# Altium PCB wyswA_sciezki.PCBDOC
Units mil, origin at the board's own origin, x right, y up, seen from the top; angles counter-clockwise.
Board outline 7130 x 4885 mil, 2 copper layers (Top Layer, Bottom Layer); 14 components, 44 nets, 417 pads, 152 vias.
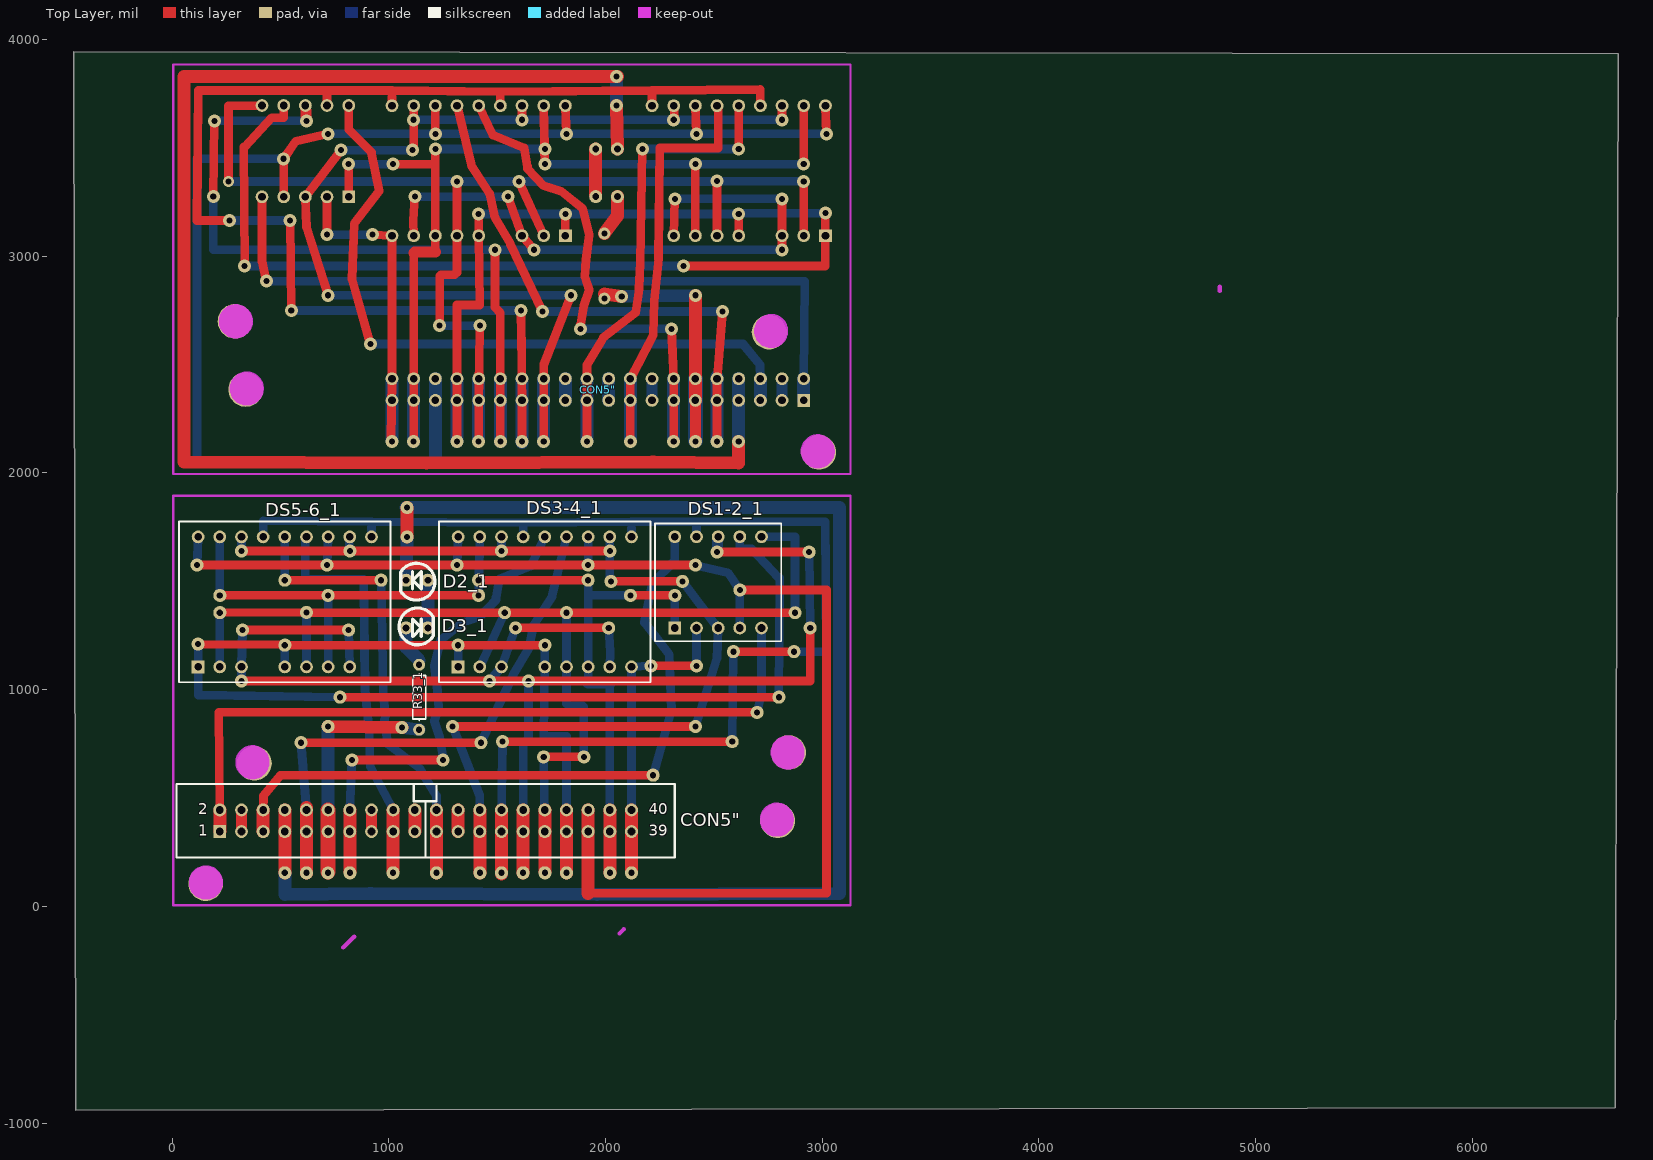
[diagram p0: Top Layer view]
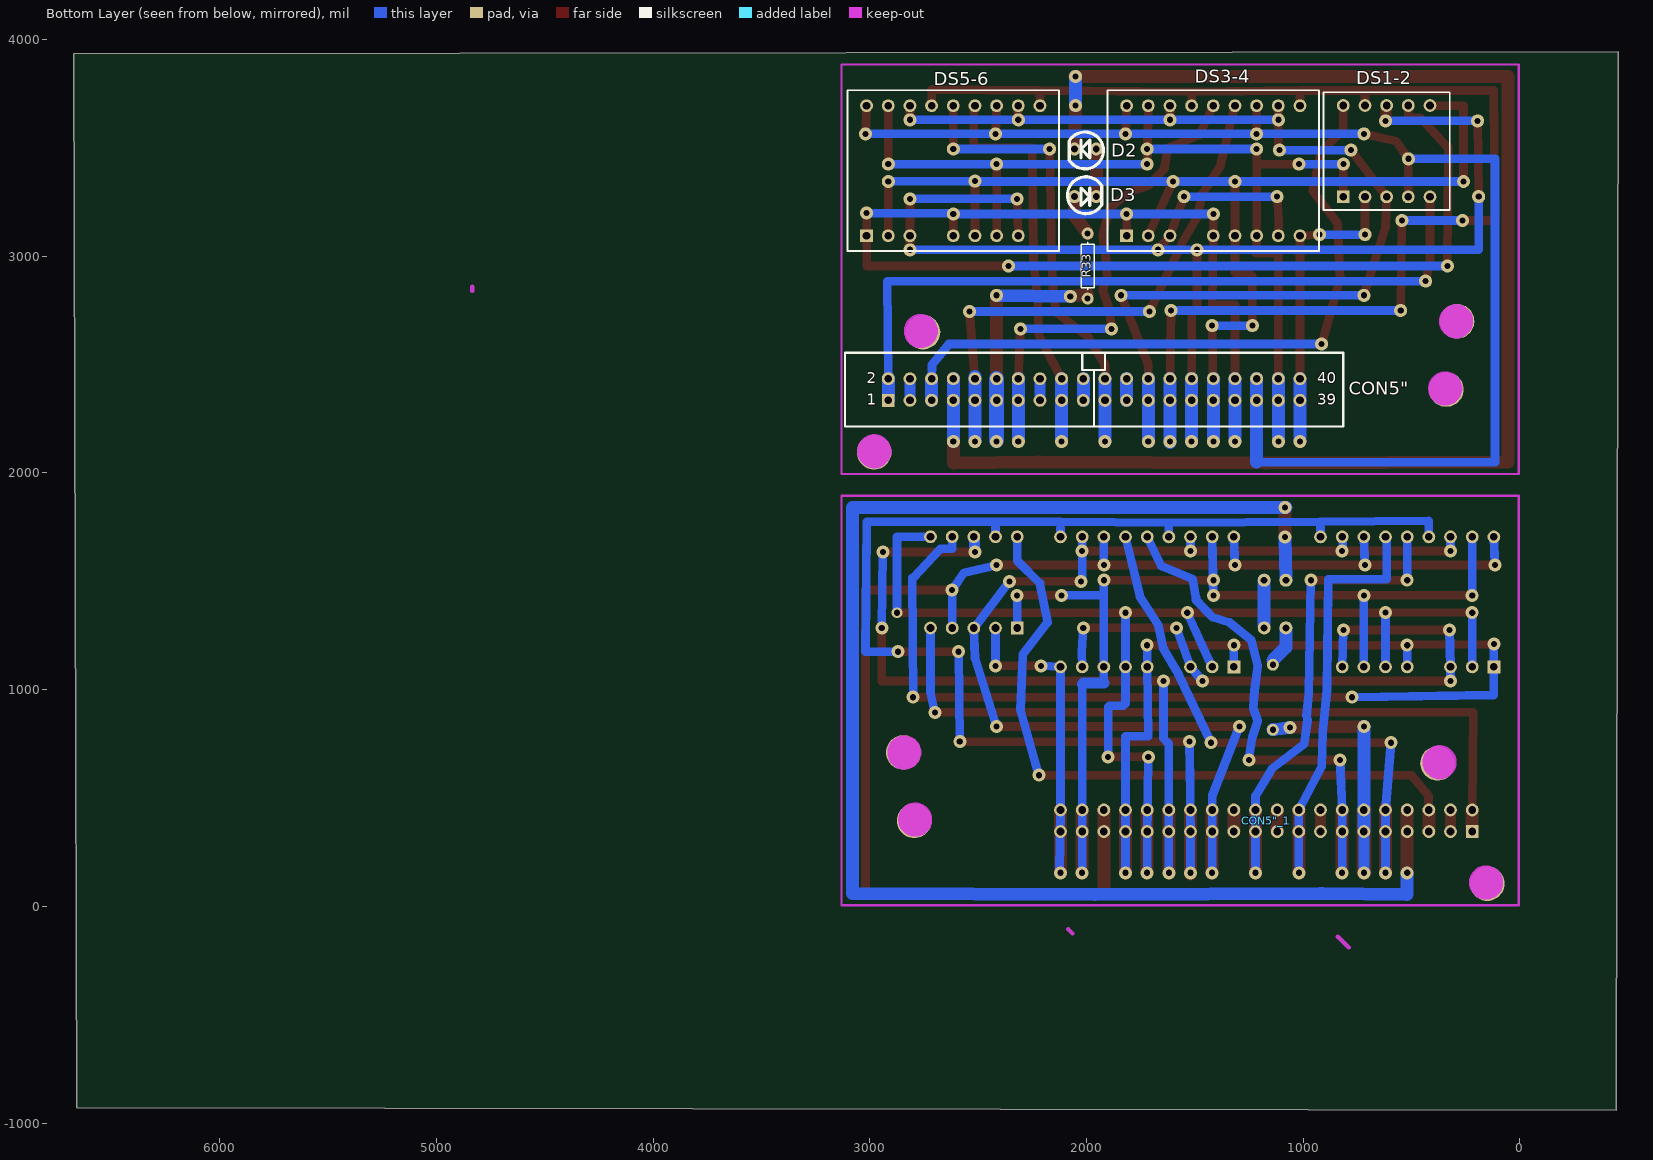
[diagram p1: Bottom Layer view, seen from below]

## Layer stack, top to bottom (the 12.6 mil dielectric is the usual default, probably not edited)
Top Layer: signal copper 1.4
Dielectric: dielectric 12.6, FR-4, Dk 4.8
Bottom Layer: signal copper 1.4

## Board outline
-445,-940 6660,-930 6675,3935 -455,3945

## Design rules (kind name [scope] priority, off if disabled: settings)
Clearance [All] p1: gap=10
ComponentClearance [All] p1: gap=1 collisioncheckmode=0
PolygonConnect [All] p1: connectstyle=Relief reliefconductorwidth=10 reliefentries=4 polygonreliefangle="90 Angle"
RoutingLayers [All] p1: top layer=Horizontal bottom layer=Vertical
RoutingVias [All] p1: holewidth=28 width=50 viastyle="Through Hole" minholewidth=28 minwidth=50 maxholewidth=28 maxwidth=50
SolderMaskExpansion [All] p1: expansion=4
TestPointUsage [All] p1: valid=0 allowmultiple=FALSE
Testpoint [All] p1: side=15 testpointundercomponent=TRUE minsize=40 maxsize=100 preferedsize=60 minholesize=0 maxholesize=40 preferedholesize=32 testpointgrid=1 style=1023 order=1234567890
Width [All] p1: maxlimit=90 minlimit=10 preferedwidth=10 toplayer_prefwidth=50 bottomlayer_prefwidth=50 minimp=50.000000 maximp=50.000000 favimp=50.000000
16 further rules are at their usual default settings.

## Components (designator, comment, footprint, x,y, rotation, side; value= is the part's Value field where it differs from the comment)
"CON5\"" "Header 20X2H" HDR2X20_gn_pra 1015,2335 r0 top
"CON5\"_1" "Header 20X2H" HDR2X20_gn_pra 2120,345 r180 bottom
D2 "LED_3" LED3 1955,3495 r180 bottom (schematic designator D3)
D2_1 "LED_3" LED3 1180,1505 r0 top (schematic designator D3)
D3 "LED_3" LED3 2055,3275 r0 bottom (schematic designator D4)
D3_1 "LED_3" LED3 1080,1285 r180 top (schematic designator D4)
DS1-2 "*" LEDDIP-DA/DC36 615,3485 r180 bottom (schematic designator DS12)
DS1-2_1 "*" LEDDIP-DA/DC36 2520,1495 r0 top (schematic designator DS12)
DS3-4 "*" LEDDIP-DA/DC56#1 1415,3395 r180 bottom (schematic designator DS34)
DS3-4_1 "*" LEDDIP-DA/DC56#1 1720,1405 r0 top (schematic designator DS34)
DS5-6 "*" LEDDIP-DA/DC56#2 2615,3395 r180 bottom (schematic designator DS56)
DS5-6_1 "*" LEDDIP-DA/DC56#2 520,1405 r0 top (schematic designator DS56)
R33 "Res2" AXIAL-0.3 1995,2955 r90 bottom
R33_1 "Res2" AXIAL-0.3 1140,965 r90 top (schematic designator R33)

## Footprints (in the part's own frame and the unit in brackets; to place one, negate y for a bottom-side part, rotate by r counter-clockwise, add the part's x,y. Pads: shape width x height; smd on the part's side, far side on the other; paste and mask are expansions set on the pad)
AXIAL-0.3 [mm]
  round 1.4 hole 0.711: 1(-3.81,0) 2(3.81,0)
  silkscreen extent -2.77,-0.76 2.77,0.76
HDR2X20_gn_pra [mm]
  rect 1.5x1.5 hole 0.9: 1(48.26,0)
  round 1.5 hole 0.9: 2(48.26,2.54) 3(45.72,0) 4(45.72,2.54) 5(43.18,0) 6(43.18,2.54) 7(40.64,0) 8(40.64,2.54) 9(38.1,0) 10(38.1,2.54) 11(35.56,0) 12(35.56,2.54) 13(33.02,0) 14(33.02,2.54) 15(30.48,0) 16(30.48,2.54) 17(27.94,0) 18(27.94,2.54) 19(25.4,0) 20(25.4,2.54) 21(22.86,0) 22(22.86,2.54) 23(20.32,0) 24(20.32,2.54) 25(17.78,0) 26(17.78,2.54) 27(15.24,0) 28(15.24,2.54) 29(12.7,0) 30(12.7,2.54) 31(10.16,0) 32(10.16,2.54) 33(7.62,0) 34(7.62,2.54) 35(5.08,0) 36(5.08,2.54) 37(2.54,0) 38(2.54,2.54) 39(0,0) 40(0,2.54)
LED3 [mil]
  round 60 hole 32: 1(0,0) 2(-100,0)
  silkscreen extent -125,-92 33,78
LEDDIP-DA/DC36 [mm]
  rect 1.5x1.5 hole 0.9: 1(-5.08,-5.35)
  round 1.5 hole 0.9: 2(-2.54,-5.35) 3(0,-5.35) 4(2.54,-5.35) 5(5.08,-5.35) 6(5.08,5.35) 7(2.54,5.35) 8(0,5.35) 9(-2.54,5.35) 10(-5.08,5.35)
  silkscreen extent -7.4,-6.9 7.4,6.9
LEDDIP-DA/DC56#1 [mm]
  rect 1.5x1.5 hole 0.9: 1(-10.16,-7.62)
  round 1.5 hole 0.9: 2(-7.62,-7.62) 3(-5.08,-7.62) 5(0,-7.62) 6(2.54,-7.62) 7(5.08,-7.62) 8(7.62,-7.62) 9(10.16,-7.62) 10(10.16,7.62) 11(7.62,7.62) 12(5.08,7.62) 13(2.54,7.62) 14(0,7.62) 15(-2.54,7.62) 16(-5.08,7.62) 17(-7.62,7.62) 18(-10.16,7.62)
  silkscreen extent -12.4,-9.43 12.4,9.43
LEDDIP-DA/DC56#2 [mm]
  rect 1.5x1.5 hole 0.9: 1(-10.16,-7.62)
  round 1.5 hole 0.9: 2(-7.62,-7.62) 3(-5.08,-7.62) 5(0,-7.62) 6(2.54,-7.62) 7(5.08,-7.62) 8(7.62,-7.62) 10(10.16,7.62) 11(7.62,7.62) 12(5.08,7.62) 13(2.54,7.62) 14(0,7.62) 15(-2.54,7.62) 16(-5.08,7.62) 17(-7.62,7.62) 18(-10.16,7.62)
  silkscreen extent -12.4,-9.43 12.4,9.43

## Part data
D2 D2_1 D3 D3_1: "Typical RED, GREEN, YELLOW, AMBER GaAs LED"
DS1-2 DS1-2_1: library part DA36, "Common Anode Dual Seven-Segment Display, Right Hand Decimal"
DS3-4 DS3-4_1 DS5-6 DS5-6_1: library part DA56, "Common Anode Dual Seven-Segment Display, Right Hand Decimal"
R33 R33_1: "Resistor"

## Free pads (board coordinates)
  round 60 smd: 0(220,345) 0(1060,825) 0(1645,1040) 1(720,830) 1(1220,445) 1(1520,1640) 1(1920,445) 1(2220,605) 2(820,1640) 2(1920,345) 3(520,155) 3(1535,1355) 4(620,155) 4(2020,445) 4(2700,895) 5(2020,345) 6(820,155) 6(1920,1575) 8(720,1435) 8(1020,155) 9(115,1575) 10(715,1575) 10(1220,155) 11(1315,1575) 12(1085,1840) 12(1420,155) 12(1920,1575) 13(1085,1705) 13(1520,155) 13(2415,1575) 14(1620,155) 14(2620,1460) 15(1720,155) 15(2020,1640) 16(1820,155) 18(2020,155) 18(2120,445) 18(2515,1635) 19(2120,155) 19(2120,345) 20(2210,1110) 21(2420,1110) 23(1820,445) 24(1820,345) 26(1720,445) 27(1720,345) 28(1720,345) 29(1715,690) 30(1900,690) 32(1620,445) 33(1620,345) 35(2945,1285) 37(1520,445) 38(1415,1505) 38(1520,345) 39(1920,1505) 39(2585,760) 40(2025,1500) 41(1420,445) 41(2355,1500) 42(220,1435) 42(1420,345) 43(1295,830) 44(1415,1435) 44(2415,830) 45(2025,1500) 45(2115,1435) 46(2320,1435) 46(2355,1500) 47(220,1355) 48(619.99,1356.48) 49(1820,1355) 50(2875,1355) 51(325,1275) 52(815,1275) 53(520,445) 53(1585,1285) 54(2015,1285) 55(120,1210) 55(520,345) 56(520,1205) 57(1720,1205) 58(1220,345) 58(2590,1175) 59(965,1505) 60(520,1505) 62(2800,965) 63(775,965) 64(320,1040) 65(720,445) 66(720,345) 67(2420,1110) 68(2870,1175) 70(1320,1205) 71(220,445) 73(1465,1040) 77(420,445) 78(420,345) 80(620,445) 81(620,345) 82(595,755) 83(1425,755) 84(820,445) 86(820,345) 87(830,675) 88(1250,675) 89(1020,445) 91(1020,345) 98(320,1640) 100(2940,1635) 101(1525,760)
  round 30 on Keep-Out: 0(1490,-110)
  round 60 smd far side: 0(1490,3030) 0(2075,2815) 0(2915,2335) 1(915,2595) 1(1215,2435) 1(1615,3630) 1(1915,2435) 1(2415,2820) 2(1215,2335) 2(2315,3630) 3(1600,3345) 3(2615,2145) 4(435,2885) 4(1115,2435) 4(2515,2145) 5(1115,2335) 6(1215,3565) 6(2315,2145) 8(2115,2145) 8(2415,3425) 9(3020,3565) 10(1915,2145) 10(2420,3565) 11(1820,3565) 12(1215,3565) 12(1715,2145) 12(2050,3830) 13(720,3565) 13(1615,2145) 13(2050,3695) 14(515,3450) 14(1515,2145) 15(1115,3630) 15(1415,2145) 16(1315,2145) 18(620,3625) 18(1015,2435) 18(1115,2145) 19(1015,2145) 19(1015,2335) 20(925,3100) 21(715,3100) 23(1315,2435) 24(1315,2335) 26(1415,2435) 27(1415,2335) 28(1415,2335) 29(1420,2680) 30(1235,2680) 32(1515,2435) 33(1515,2335) 35(190,3275) 37(1615,2435) 38(1615,2335) 38(1720,3495) 39(550,2750) 39(1215,3495) 40(1110,3490) 41(780,3490) 41(1715,2435) 42(1715,2335) 42(2915,3425) 43(1840,2820) 44(720,2820) 44(1720,3425) 45(1020,3425) 45(1110,3490) 46(780,3490) 46(815,3425) 47(2915,3345) 48(2515.01,3346.48) 49(1315,3345) 50(260,3345) 51(2815,3265) 52(2320,3265) 53(1550,3275) 53(2615,2435) 54(1120,3275) 55(2615,2335) 55(3015,3200) 56(2615,3195) 57(1415,3195) 58(545,3165) 58(1915,2335) 59(2170,3495) 60(2615,3495) 62(335,2955) 63(2360,2955) 64(2815,3030) 65(2415,2435) 66(2415,2335) 67(715,3100) 68(265,3165) 70(1815,3195) 71(2915,2435) 73(1670,3030) 77(2715,2435) 78(2715,2335) 80(2515,2435) 81(2515,2335) 82(2540,2745) 83(1710,2745) 84(2315,2435) 86(2315,2335) 87(2305,2665) 88(1885,2665) 89(2115,2435) 91(2115,2335) 98(2815,3630) 100(195,3625) 101(1610,2750)
  round 160 smd: 9(290,2700) 10(340,2385) 11(2755,2650) 12(2985,2095) 13(380,660) 14(2845,710) 15(2795,395) 16(155,105)
  round 160 smd far side: 9(2845,710) 10(2795,395) 11(380,660) 12(150,105) 13(2755,2650) 14(290,2700) 15(340,2385) 16(2980,2095)

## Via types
v1: diameter 60, hole 28, Top Layer to Bottom Layer, 148 vias
v2: diameter 50, hole 28, Top Layer to Bottom Layer, 4 vias

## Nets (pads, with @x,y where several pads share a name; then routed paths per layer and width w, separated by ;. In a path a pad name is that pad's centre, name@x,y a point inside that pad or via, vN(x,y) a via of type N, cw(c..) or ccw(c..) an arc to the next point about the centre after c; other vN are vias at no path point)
A: 
"A1\"": "CON5\".1" "CON5\".2" DS1-2.5 pad.0@2915,2335 pad.4@435,2885 pad.71@2915,2435 | length 3451.6
  Top Layer w40: DS1-2.5 415,2975 v1(435,2885)
  Bottom Layer w40: v1(435,2885) 1350,2885 ; 1325,2885 2920,2885 v2(2915,2435)
  Bottom Layer w60: pad.0@2915,2335 v2(2915,2435)
"A2\"": "CON5\".5" "CON5\".6" DS1-2.10 pad.1@915,2595 pad.77@2715,2435 pad.78@2715,2335 | length 3206.5
  Top Layer w40: DS1-2.10 815,3585 920,3480 955,3300 840,3150 830,2895 v1(915,2595)
  Bottom Layer w40: v1(915,2595) 2635,2595 2713.09,2499.94 pad.77@2715,2435
  Bottom Layer w60: pad.78@2715,2335 pad.77@2715,2435
"A3\"": "CON5\".9" "CON5\".10" DS3-4.13 pad.4@2515,2145 pad.80@2515,2435 pad.81@2515,2335 pad.82@2540,2745 pad.83@1710,2745 | length 2749.7
  Top Layer w40: DS3-4.13 1380,3425 ; 1380,3420 1465,3290 1490,3180 1560,3060 v1(1710,2745) ; v1(2515,2145) 2515,2320 ; 2515,2335 2515,2435 v1(2540,2745)
  Bottom Layer w40: v1(1710,2745) v1(2540,2745)
  Bottom Layer w60: v1(2515,2145) 2515,2335 pad.80@2515,2445
"A4\"": "CON5\".13" "CON5\".14" DS3-4.14 pad.6@2315,2145 pad.84@2315,2435 pad.86@2315,2335 pad.87@2305,2665 pad.88@1885,2665 | length 2488.3
  Top Layer w40: DS3-4.14 1480,3560 1625,3500 1640,3415 ; 1640,3405 1715,3325 1795,3300 1895,3220 1925,3100 1910,2985 1905,2905 1925,2845 1900,2770 v1@1885,2685 ; v1(2305,2665) 2315,2435 2315,2335 v1(2315,2145)
  Bottom Layer w40: v1(1885,2665) v1(2305,2665)
  Bottom Layer w60: pad.6@2315,2150 2315,2335 pad.84@2315,2435
"A5\"": "CON5\".17" "CON5\".18" DS5-6.13 pad.8@2115,2145 pad.89@2115,2435 pad.91@2115,2335 | length 2107
  Top Layer w40: v1@2115,2155 2115,2335 2115,2435 2220,2635 2225,2795 2245,2990 2250,3500 2520,3500 DS5-6.13@2520,3680
  Bottom Layer w60: pad.8@2115,2155 pad.91@2115,2335 ; pad.91@2115,2330 pad.89@2115,2435
  other v1: 2115,2145
"A6\"": "CON5\".21" "CON5\".22" DS5-6.14 pad.1@1915,2435 pad.10@1915,2145 pad.58@1915,2335 pad.59@2170,3495 pad.60@2615,3495 | length 2379.9
  Top Layer w40: v1@1915,2140 1915,2335 1915,2500 1985,2615 ; 1990,2625 2140,2740 2155,2850 2160,2970 v1(2170,3495) ; v1(2615,3495) DS5-6.14
  Bottom Layer w40: v1(2170,3495) pad.60@2620,3495
  Bottom Layer w60: v1(1915,2145) 1915,2335 pad.1@1915,2435
A7: 
A8: 
A9: 
A10: 
A11: 
A12: 
"A\"": "CON5\".25" "CON5\".26" DS1-2.3 DS3-4.11 DS3-4.16 DS5-6.11 DS5-6.16 pad.1@1615,3630 pad.2@2315,3630 pad.12@1715,2145 pad.15@1115,3630 pad.40@1110,3490 pad.41@780,3490 pad.41@1715,2435 pad.42@1715,2335 pad.43@1840,2820 pad.44@720,2820 pad.45@1110,3490 pad.46@780,3490 pad.98@2815,3630 | length 5260.2
  Top Layer w40: v1(720,2820) 620,3135 DS1-2.3 v1(780,3490) ; v1@1115,3500 DS3-4.11 ; v1(1615,3630) DS3-4.16 ; v1@1715,2140 1715,2335 1715,2500 v1(1840,2820) ; DS5-6.11 v1@2320,3635 ; v1(2815,3630) DS5-6.16
  Bottom Layer w40: v1(720,2820) v1(1840,2820) ; v1(780,3490) pad.40@1100,3490 ; v1(1115,3630) v1(2815,3630)
  Bottom Layer w60: v1(1715,2145) 1715,2335 pad.41@1715,2435
  other v1: 1110,3490 2315,3630
B: 
"B\"": "CON5\".27" "CON5\".28" DS1-2.9 DS3-4.10 DS3-4.15 DS5-6.10 DS5-6.15 pad.13@1615,2145 pad.37@1615,2435 pad.38@1615,2335 pad.39@550,2750 pad.58@545,3165 pad.68@265,3165 pad.101@1610,2750 | length 6249.5
  Top Layer w40: 120,3760 115,3165 v1(265,3165) ; 120,3765 710,3765 1015,3765 1520,3760 2215,3765 2715,3770 DS5-6.15 ; v1(545,3165) v1(550,2750) ; DS1-2.9 715,3740 ; DS3-4.10 1015,3735 ; DS3-4.15 1515,3745 ; v1(1610,2750) 1612.95,2504.98 1613.8,2434.99 1615,2335 v1(1615,2145) ; DS5-6.10 2215,3740
  Bottom Layer w40: v1(265,3165) v1(545,3165) ; v1(550,2750) v1(1610,2750)
  Bottom Layer w60: pad.13@1615,2140 1615,2320 pad.37@1615,2435
C: 
"C\"": "CON5\".29" "CON5\".30" DS1-2.8 DS3-4.3 DS3-4.8 DS5-6.3 DS5-6.8 pad.0@1490,3030 pad.14@1515,2145 pad.18@620,3625 pad.32@1515,2435 pad.33@1515,2335 pad.35@190,3275 pad.51@2815,3265 pad.52@2320,3265 pad.53@1550,3275 pad.54@1120,3275 pad.64@2815,3030 pad.73@1670,3030 pad.100@195,3625 | length 6685.2
  Top Layer w30: DS3-4.8@1110,3090 DS3-4.8
  Top Layer w40: v1(190,3275) v1(195,3625) ; DS3-4.8 1112.27,3164.93 v1(1120,3275) ; v1@1490,3025 1490,2765 1515,2740 1515,2335 v1(1515,2145) ; v1(1550,3275) DS3-4.3 v1(1670,3030) ; DS5-6.8 v1(2320,3265) ; v1(2815,3030) DS5-6.3 v1(2815,3265)
  Top Layer w50: DS1-2.8 v1(620,3625)
  Bottom Layer w40: v1(190,3275) 190,3030 v1(1490,3030) pad.73@1665,3030 ; v1(195,3625) v1(620,3625) ; v1(1120,3275) v1(1550,3275) ; v1(1670,3030) v1(2815,3030) ; v1(2320,3265) v1(2815,3265)
  Bottom Layer w60: v1(1515,2145) 1515,2335 pad.32@1515,2435
D: 
"D\"": "CON5\".31" "CON5\".32" DS1-2.6 DS3-4.2 DS3-4.6 DS5-6.2 DS5-6.6 pad.3@1600,3345 pad.15@1415,2145 pad.26@1415,2435 pad.27@1415,2335 pad.28@1415,2335 pad.29@1420,2680 pad.30@1235,2680 pad.47@2915,3345 pad.48@2515.01,3346.48 pad.49@1315,3345 pad.50@260,3345 | length 5631.7
  Top Layer w40: v2(260,3345) 260,3695 DS1-2.6 ; v1@1235,2700 1235,2910 ; 1240,2915 1305,2915 ; 1315,2925 DS3-4.6 v1(1315,3345) ; v1@1415,2150 1415,2335 1416.45,2434.98 1417.39,2499.97 v1(1420,2680) ; v1(1600,3345) DS3-4.2 ; DS5-6.6 v1(2515.01,3346.48) ; DS5-6.2 v1(2915,3345)
  Bottom Layer w40: v2(260,3345) pad.48@2515.01,3345 ; v1(1235,2680) v1(1420,2680) ; v1(2515.01,3346.48) v1(2915,3345)
  Bottom Layer w60: pad.15@1415,2150 1415,2335 pad.26@1415,2435
  other v1: 1415,2145
DP: 
"DP\"": "CON5\".39" "CON5\".40" DS1-2.2 DS3-4.9 pad.18@1015,2435 pad.19@1015,2145 pad.19@1015,2335 pad.20@925,3100 pad.21@715,3100 pad.67@715,3100 | length 1689.6
  Top Layer w40: v1(715,3100) DS1-2.2@715,3259.37 ; v1(925,3100) DS3-4.9 1015,2505 1015,2435 v1@1010,2150
  Bottom Layer w40: v1(715,3100) v1(925,3100)
  Bottom Layer w60: pad.19@1015,2150 1015,2335 pad.18@1015,2435
  other v1: 1015,2145
E: 
"E\"": "CON5\".33" "CON5\".34" DS1-2.7 DS3-4.1 DS3-4.5 DS5-6.1 DS5-6.5 pad.16@1315,2145 pad.23@1315,2435 pad.24@1315,2335 pad.55@3015,3200 pad.56@2615,3195 pad.57@1415,3195 pad.62@335,2955 pad.63@2360,2955 pad.70@1815,3195 | length 6984.7
  Top Layer w40: 330,3505 v1(335,2955) ; 335,3505 460,3640 515,3640 DS1-2.7 ; v1(1315,2145) 1315,2335 1315,2765 ; 1315,2775 1420,2775 DS3-4.5 ; DS3-4.5@1415,3105 v1(1415,3195) ; DS3-4.1 v1(1815,3195) ; v1(2360,2955) 3015,2955 DS5-6.1 v1(3015,3200) ; DS5-6.5@2615,3105 v1(2615,3195)
  Bottom Layer w40: v1(335,2955) v1(2360,2955) ; v1(1415,3195) v1(1815,3195) v1(2615,3195) ; pad.56@2614.98,3197.49 v1(3015,3200)
  Bottom Layer w60: v1(1315,2145) 1315,2335 pad.23@1315,2435
F: 
"F\"": "CON5\".35" "CON5\".36" DS1-2.4 DS3-4.12 DS3-4.18 DS5-6.12 DS5-6.18 pad.1@1215,2435 pad.2@1215,2335 pad.6@1215,3565 pad.9@3020,3565 pad.10@2420,3565 pad.11@1820,3565 pad.12@1215,3565 pad.13@720,3565 pad.14@515,3450 | length 6522
  Top Layer w40: DS1-2.4 v1(515,3450) 570,3530 v1(720,3565) ; v1@1215,3575 DS3-4.12 ; DS3-4.18 v1(1820,3565) ; DS5-6.12 v1(2420,3565) ; DS5-6.18 v1(3020,3565)
  Bottom Layer w40: v1(515,3450) 115,3450 115,2050 1215,2050 ; v1(720,3565) v1(3020,3565)
  Bottom Layer w60: 1215,2050 pad.1@1215,2435
  other v1: 1215,3565
G: 
"G\"": "CON5\".37" "CON5\".38" DS1-2.1 DS3-4.7 DS3-4.17 DS5-6.7 DS5-6.17 pad.4@1115,2435 pad.5@1115,2335 pad.8@2415,3425 pad.18@1115,2145 pad.38@1720,3495 pad.39@1215,3495 pad.42@2915,3425 pad.44@1720,3425 pad.45@1020,3425 pad.46@815,3425 | length 4857.7
  Top Layer w40: DS1-2.1 v1(815,3425) ; v1(1020,3425) 1215,3425 ; v1(1115,2145) 1115,2335 1115,3015 ; 1215,3020 v1(1215,3495) ; DS3-4.17 1718.61,3499.97 v1(1720,3425) ; DS5-6.7 v1(2415,3425) ; v1(2915,3425) DS5-6.17
  Top Layer w50: 1115,3015 1120,3020 1215,3020
  Bottom Layer w40: v1(815,3425) v1(1020,3425) ; v1(1215,3495) v1(1720,3495) ; v1(1720,3425) v1(2915,3425)
  Bottom Layer w60: v1(1115,2145) 1115,2335 pad.4@1115,2435
GND: 
"GND\"": "CON5\".7" "CON5\".8" D2.2 pad.3@2615,2145 pad.12@2050,3830 pad.13@2050,3695 pad.53@2615,2435 pad.55@2615,2335 | length 7072.2
  Top Layer w50: 2614.94,2045 2615,2045 ; 2615,2050 2620,2045
  Top Layer w60: 55,2050 1175,2045 2225,2050 ; 55,2055 55,3830 v1@2055,3830 ; v1(2050,3695) D2.2 ; 2215,2050 2614.94,2045 ; 2615,2050 v1(2615,2145)
  Bottom Layer w60: v1(2050,3695) v1(2050,3830) ; v1(2615,2145) 2615,2335 pad.53@2615,2435
NC1: 
"NC1\"": "CON5\".3" "CON5\".4" | length 100
  Bottom Layer w50: 2815,2335 2815,2435
NC2: 
"NC2\"": "CON5\".15" "CON5\".16" | length 100
  Bottom Layer w50: 2215,2335 2215,2435
NC3: 
"NC3\"": "CON5\".19" "CON5\".20" | length 100
  Bottom Layer w60: 2015,2335 2015,2435
NC4: 
"NC4\"": "CON5\".23" "CON5\".24" | length 100
  Bottom Layer w60: 1815,2335 1815,2435
NetD2_1: D2.1 D3.2 | length 210
  Top Layer w60: D3.2@1955,3285 D2.1
NetD3_1: D3.1 R33.2 | length 190
  Top Layer w60: R33.2 2055,3185 D3.1
NetD4_1: 
NetD5_1: 
VCC: 
"VCC\"": "CON5\".11" "CON5\".12" pad.0@2075,2815 pad.1@2415,2820 pad.65@2415,2435 pad.66@2415,2335 R33.1 | length 1387.7
  Top Layer w50: 2415,2335 v1(2415,2145) v1@2420,2150
  Top Layer w60: R33.1@1995,2825 v1(2075,2815) ; 2415,2335 v1(2415,2820)
  Bottom Layer w60: v1(2075,2815) v1(2415,2820)
  Bottom Layer w70: v1@2415,2150 pad.65@2415,2435
pads on no net: "CON5\"_1.1" "CON5\"_1.2" "CON5\"_1.3" "CON5\"_1.4" "CON5\"_1.5" "CON5\"_1.6" "CON5\"_1.7" "CON5\"_1.8" "CON5\"_1.9" "CON5\"_1.10" "CON5\"_1.11" "CON5\"_1.12" "CON5\"_1.13" "CON5\"_1.14" "CON5\"_1.15" "CON5\"_1.16" "CON5\"_1.17" "CON5\"_1.18" "CON5\"_1.19" "CON5\"_1.20" "CON5\"_1.21" "CON5\"_1.22" "CON5\"_1.23" "CON5\"_1.24" "CON5\"_1.25" "CON5\"_1.26" "CON5\"_1.27" "CON5\"_1.28" "CON5\"_1.29" "CON5\"_1.30" "CON5\"_1.31" "CON5\"_1.32" "CON5\"_1.33" "CON5\"_1.34" "CON5\"_1.35" "CON5\"_1.36" "CON5\"_1.37" "CON5\"_1.38" "CON5\"_1.39" "CON5\"_1.40" D2_1.1 D2_1.2 D3_1.1 D3_1.2 DS1-2_1.1 DS1-2_1.2 DS1-2_1.3 DS1-2_1.4 DS1-2_1.5 DS1-2_1.6 DS1-2_1.7 DS1-2_1.8 DS1-2_1.9 DS1-2_1.10 DS3-4_1.1 DS3-4_1.2 DS3-4_1.3 DS3-4_1.5 DS3-4_1.6 DS3-4_1.7 DS3-4_1.8 DS3-4_1.9 DS3-4_1.10 DS3-4_1.11 DS3-4_1.12 DS3-4_1.13 DS3-4_1.14 DS3-4_1.15 DS3-4_1.16 DS3-4_1.17 DS3-4_1.18 DS5-6_1.1 DS5-6_1.2 DS5-6_1.3 DS5-6_1.5 DS5-6_1.6 DS5-6_1.7 DS5-6_1.8 DS5-6_1.10 DS5-6_1.11 DS5-6_1.12 DS5-6_1.13 DS5-6_1.14 DS5-6_1.15 DS5-6_1.16 DS5-6_1.17 DS5-6_1.18 R33_1.1 R33_1.2
copper on no net: | length 69473.9
  Top Layer w40: v1(115,1575) v1(2415,1575) ; v1(120,1210) v1@520.02,1207.49 ; v2(220,445) 215,895 1810,895 ; v1(220,1355) v1(619.99,1356.48) ; v1(220,1435) v1(1415,1435) ; v1(320,1040) v1(1465,1040) ; v1(320,1640) v1(2020,1640) ; v1(325,1275) v1(815,1275) ; 420,445 421.91,509.94 500,605 v1(2220,605) ; v1@515,1505 v1(965,1505) ; v1(520,1205) v1(1320,1205) v1(1720,1205) ; v1(595,755) v1(1425,755) ; v1@619.99,1355 v2(2875,1355) ; v1(775,965) v1(2800,965) ; v1(830,675) v1(1250,675) ; v1(1295,830) v1(2415,830) ; v1(1415,1505) v1(1920,1505) ; v1@1470,1040 v1(1645,1040) 2945,1040 v1(2945,1285) ; v1(1525,760) v1(2585,760) ; v1(1585,1285) v1(2015,1285) ; v1(1715,690) v1(1900,690) ; 1785,895 v1(2700,895) ; 1920,60 3020,60 3020,1460 v1(2620,1460) ; v1@2035,1500 v1(2355,1500) ; v1(2115,1435) v1(2320,1435) ; v1(2210,1110) v1(2420,1110) ; v1(2515,1635) v1(2940,1635) ; v1(2590,1175) v1(2870,1175)
  Top Layer w50: 320,345 320,445 ; 920,345 920,445
  Top Layer w60: 220,345 v2(220,445) ; 420,345 420,445 ; v1(520,155) 520,345 520,445 ; v1(620,155) 620,345 620,455 ; v1(720,830) v1(1060,825) ; v1@820,160 820,345 820,445 ; v1@1020,165 1020,345 ; 1020,340 1020,445 ; v1(1085,1705) v1(1085,1840) ; 1120,345 1120,445 ; v1(1220,155) 1220,345 1220,445 ; 1320,345 1320,445 ; v1(1420,155) 1420,345 1420,445 ; v1@1520,150 1520,330 1520,445 ; v1(1620,155) 1620,345 1620,445 ; v1@1720,160 1720,345 1720,445 ; v1(1820,155) 1820,345 1820,445 ; 1920,60 1920,445 ; v1(2020,155) 2020,345 2020,445 ; v1@2120,160 2120,345 2120,445
  Top Layer w70: v1@720,160 720,445
  Bottom Layer w30: 2020,1105 2025,1100
  Bottom Layer w40: v1(115,1575) 120,1705 ; v1(120,1210) 120,1105 120,975 v1(775,965) ; 220,1105 v1(220,1355) ; v1(220,1435) 220,1705 ; v1(320,1040) 320,1105 v1(325,1275) ; v1(320,1640) 320,1705 ; 420,1705 420,1780 920,1775 1615,1770 2120,1775 2425,1775 3015,1775 ; 520,1115 v1(520,1205) ; v1(520,1505) 520,1705 ; v1(595,755) 620,445 620,345 ; 615,1690 615,1510 885,1510 890,1000 910,805 915,645 1020,445 1020,345 v1@1020,165 ; v1(620,155) 620,330 ; 620,1105 v1(619.99,1356.48) ; v1(715,1575) 720,1705 ; 720,1105 v1(720,1435) ; v1(815,1275) 820,1105 ; v1@815,1645 820,1705 ; v1(820,155) 820,345 820,445 v1(830,675) ; 920,1705 920,1750 ; v1(965,1505) 975,980 985,880 ; 980,860 995,750 1145,635 ; 1150,625 1220,510 1220,345 v1@1220,150 ; v1@1250,695 1235,780 1210,855 1230,915 1225,995 1210,1110 1240,1230 1340,1310 1420,1335 1495,1415 ; v1(1295,830) 1420,510 1420,345 v1@1420,150 ; v1(1315,1575) 1320,1705 ; 1320,1105 v1(1320,1205) ; v1(1415,1435) 1416.39,1509.97 1420,1705 ; 1420,1105 v1(1535,1355) ; v1(1425,755) 1575,1070 1645,1190 1670,1300 1755,1430 ; v1(1465,1040) 1520,1105 v1(1585,1285) ; 1495,1425 1510,1510 1655,1570 1720,1705 ; v1(1520,155) 1520,345 1521.2,444.99 1522.05,514.98 v1(1525,760) ; v1(1520,1640) 1520,1705 ; v1(1620,155) 1620,345 1620,750 1645,775 v1@1645,1035 ; 1620,1705 1620,1755 ; v1(1715,690) 1717.61,509.97 1718.55,444.98 1720,345 v1@1720,160 ; 1720,1105 1715,785 1820,785 ; 1720,1115 v1(1720,1205) ; 1755,1435 1820,1705 ; v1(1820,155) 1820,345 1820,775 ; 1820,935 1820,1105 v1(1820,1355) ; 1830,925 1895,925 ; v1@1900,710 1900,920 ; 1920,1030 v1(1920,1505) ; 1920,1435 v1(2115,1435) ; v1@1920,1585 1920,1705 ; v1(2015,1285) 2022.73,1174.93 2020,1105 ; v1(2020,155) 2020,345 2020,1025 ; v1@2020,1510 2020,1705 ; 2120,1705 2120,1745 ; v1@2125,160 2120,445 2120,515 2120,1105 v1(2210,1110) ; v1(2220,605) 2305,905 2295,1160 2180,1310 2215,1490 2320,1595 2320,1705.63 ; 2320,1284.37 v1(2320,1435) ; v1(2355,1500) 2520,1284.37 2515,1145 v1(2415,830) ; v1(2415,1575) 2565,1540 v1(2620,1460) 2620,1284.37 ; v1(2420,1110) 2420,1269.37 ; 2420,1705.63 2420,1750 ; v1(2585,760) v1(2590,1175) ; 2620,1705.63 2620,1650 2675,1650 2800,1515 ; v1(2700,895) 2720,985 2720,1284.37 ; 2720,1705.63 2875,1705 v2(2875,1355) ; v1(2800,965) 2805,1515 ; v1(2870,1175) 3020,1175 3015,1770 ; v1(2940,1635) v1(2945,1285)
  Bottom Layer w50: 515,55 520,60 ; 520,55 520.06,55 ; v1@715,160 v1(720,155) 720,345 ; 1920,1030 2015,1030 2020,1025 ; v1(2515,1635) 2520,1705.63
  Bottom Layer w60: 520,60 v1(520,155) ; 520.06,55 920,60 ; 720,345 v1(720,830) ; 910,60 1960,55 3080,60 ; v1(1060,825) 1140,815 ; 1080,1285 1080,1195 1140,1135 ; 1080,1505 v1(1085,1705) ; v1@1080,1840 3080,1840 3080,65 ; 1180,1295 1180,1505
  other v1: 1020,155 1720,155 2120,155 2025,1500 1920,1575 820,1640

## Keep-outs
Keep-Out Layer:
  circle w78.74: c2764.37,2655 r39.37
  circle w78.74: c2979.37,2100 r39.37
  circle w78.74: c294.37,2700 r39.37
  circle w78.74: c344.37,2390 r39.37
  circle w78.74: c155.63,110 r39.37
  circle w78.74: c370.63,665 r39.37
  circle w78.74: c2790.63,400 r39.37
  circle w78.74: c2840.63,710 r39.37
  lines w10: 5,5 3130,5 3130,1895 5,1895 5,5 ; 5,1995 5,3885 3130,3885 3130,1995 5,1995
  lines w20: 790,-190 840,-140 ; 2065,-125 2085,-105 ; 4835,2840 4835,2860
  text "wysw_A strona elementow" at 3180,2745 h100
  text "wysw_A strona lutowania" at 3185,1010 h100
  text "Rys.9 Uklad sciezek wyswietlacza A" at 85,-235 h120

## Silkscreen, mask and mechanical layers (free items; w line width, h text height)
Top Overlay:
  text "CON5\"" at 2345,370 h60
Bottom Overlay:
  text "CON5\"" at 790,2360 h60
Mechanical 4:
  lines w10: -205,0 -200,5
